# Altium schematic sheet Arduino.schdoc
size 248 x 111 mm
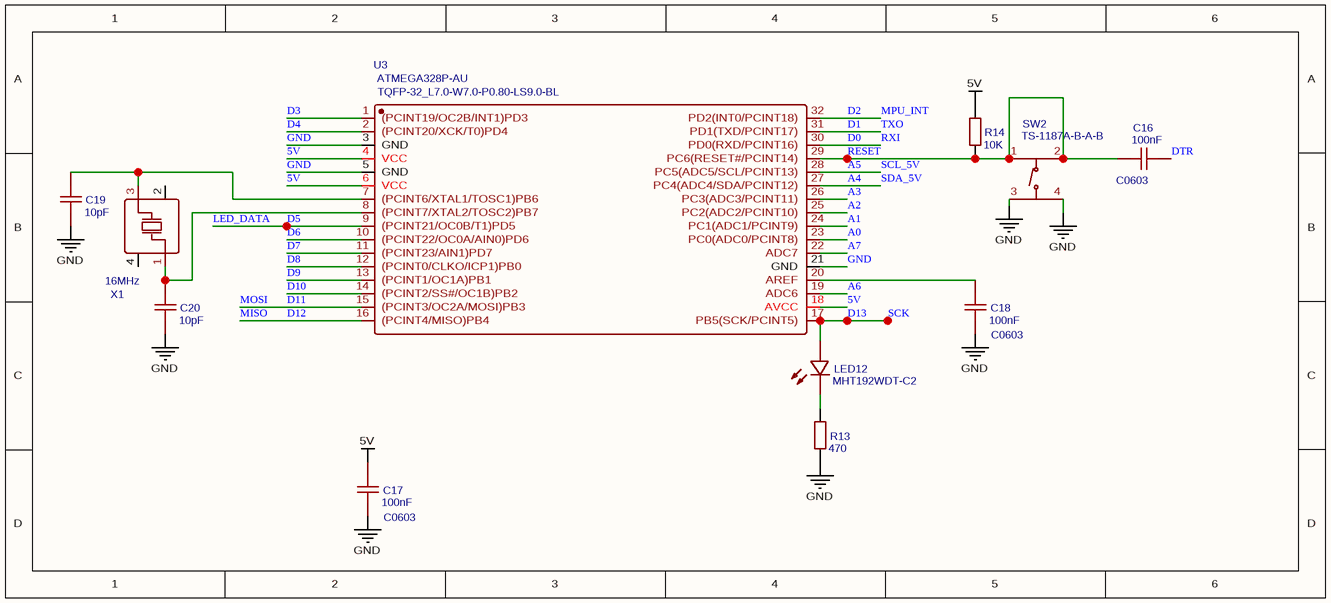
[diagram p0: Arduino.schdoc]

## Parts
C16  100nF  [C0603]
C17  100nF  [C0603]
C18  100nF  [C0603]
C19  10pF  [C0402]
C20  10pF  [C0402]
LED12  MHT192WDT-C2  [LED0603-RD]
R13  470  [R0603]
R14  10K  [R0603]
SW2  TS-1187A-B-A-B  [SW-SMD_4P-L5.1-W5.1-P3.70-LS6.4]
U3  ATMEGA328P-AU  [TQFP-32_L7.0-W7.0-P0.80-LS9.0-BL]
X1  16MHz  [OSC-SMD_4P-L3.2-W2.5-BL]

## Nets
5V: C17.1 R14.2 U3.4(VCC) U3.6(VCC) U3.18(AVCC)
GND: C17.2 C18.2 C19.1 C20.1 R13.1 SW2.3(C) SW2.4(D) U3.3(GND) U3.5(GND) U3.21(GND)
A0: U3.23(PC0(ADC0/PCINT8))
A1: U3.24(PC1(ADC1/PCINT9))
A2: U3.25(PC2(ADC2/PCINT10))
A3: U3.26(PC3(ADC3/PCINT11))
A4: U3.27(PC4(ADC4/SDA/PCINT12))  [also labelled SDA_5V]
A5: U3.28(PC5(ADC5/SCL/PCINT13))  [also labelled SCL_5V]
A6: U3.19(ADC6)
A7: U3.22(ADC7)
D0: U3.30(PD0(RXD/PCINT16))  [also labelled RXI]
D1: U3.31(PD1(TXD/PCINT17))  [also labelled TXO]
D2: U3.32(PD2(INT0/PCINT18))  [also labelled MPU_INT]
D3: U3.1((PCINT19/OC2B/INT1)PD3)
D4: U3.2((PCINT20/XCK/T0)PD4)
D5: U3.9((PCINT21/OC0B/T1)PD5)  [also labelled LED_DATA]
D6: U3.10((PCINT22/OC0A/AIN0)PD6)
D7: U3.11((PCINT23/AIN1)PD7)
D8: U3.12((PCINT0/CLKO/ICP1)PB0)
D9: U3.13((PCINT1/OC1A)PB1)
D10: U3.14((PCINT2/SS#/OC1B)PB2)
D11: U3.15((PCINT3/OC2A/MOSI)PB3)  [also labelled MOSI]
D12: U3.16((PCINT4/MISO)PB4)  [also labelled MISO]
D13: LED12.2(+) U3.17(PB5(SCK/PCINT5))  [also labelled SCK]
DTR: C16.1
RESET: C16.2 R14.1 SW2.1(A) SW2.2(B) U3.29(PC6(RESET#/PCINT14))
NetC18_1: C18.1 U3.20(AREF)
NetC19_2: C19.2 U3.7((PCINT6/XTAL1/TOSC1)PB6) X1.3(OSC2)
NetC20_2: C20.2 U3.8((PCINT7/XTAL2/TOSC2)PB7) X1.1(OSC1)
NetLED12_1: LED12.1(-) R13.2

Not connected (* = marked no-connect by the designer): X1 2(GND) 4(GND)

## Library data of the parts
C16-C18 = 100nF: BOM_Manufacturer: YAGEO; BOM_Manufacturer Part: CC0603KRX7R9BB104; nameAlias: Capacitance; SMT Type: Basic; Package Display: Yes
C19 C20 = 10pF: BOM_Manufacturer: SAMSUNG; BOM_Manufacturer Part: CL05C100JB5NNNC; nameAlias: Capacitance; SMT Type: Basic
LED12 = MHT192WDT-C2: BOM_Manufacturer: MEIHUA; Contributor: LCSC
R13 = 470: BOM_Manufacturer: UniOhm; BOM_Manufacturer Part: 0603WAF4700T5E; nameAlias: Resistance (Ohms); SMT Type: Basic
R14 = 10K: BOM_Manufacturer: UniOhm; BOM_Manufacturer Part: 0603WAF1002T5E; nameAlias: Resistance (Ohms); SMT Type: Basic
SW2 = TS-1187A-B-A-B: BOM_Manufacturer: XKB Enterprise; Contributor: LCSC
U3 = ATMEGA328P-AU: BOM_Manufacturer: MICROCHIP; SMT Type: Extend; Package Display: Yes
X1 = 16MHz: BOM_Manufacturer: YXC; BOM_Manufacturer Part: X322516MLB4SI; nameAlias: Frequency; SMT Type: Basic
